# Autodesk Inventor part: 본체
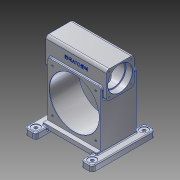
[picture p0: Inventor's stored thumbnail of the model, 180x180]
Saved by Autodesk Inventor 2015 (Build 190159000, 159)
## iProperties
Created: 2025-06
Part Number: 본체
Material: 알루미늄 6061
Document SubType Name: Modeling
Designer: User
Density: 2.7 g/cm^3
Appearance: 알루미늄 - 평지
Mass: 8003.18 g
Surface Area: 3446.16 cm^2
Volume: 2964.14 cm^3
Author: User
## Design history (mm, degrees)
sketch "스케치1"
  geometry: L1 (-93, 103)-(93, 103); L2 (93, 103)-(93, -103); L3 (93, -103)-(-93, -103); L4 (-93, -103)-(-93, 103); L5 (-93, 103)-(93, -103); L6 (93, 103)-(-93, -103); 1 further point
  constraints: 12 end point, 2 midpoint, 2 parallel, 1 horizontal, 1 perpendicular
  dimensions: "d0" = 186 distance of L2.end L3.end; "d1" = 206 distance of L1.end L2.end
extrude "돌출1" new body sketch "스케치1" stored distance "d2" = 140; taper "d3" = 0 deg
sketch "스케치3"
  geometry: L1 (0, 0)-(186, 0) reference; L2 (186, -140)-(0, -140) reference; L3 (201, -180)-(181, -180); L4 (171, -170)-(171, 30); L5 (181, 40)-(201, 40); L6 (211, 30)-(211, -170); L7 (93, -140)-(93, 0); L8 (15, -170)-(15, 30); L9 (-25, 30)-(-25, -170); L10 (-15, -180)-(5, -180); L11 (5, 40)-(-15, 40); A1 r 10 centre (201, -170) between (201, -180) and (211, -170); A2 r 10 centre (181, -170) between (171, -170) and (181, -180); A3 r 10 centre (201, 30) between (211, 30) and (201, 40); A4 r 10 centre (181, 30) between (181, 40) and (171, 30); A5 r 10 centre (-15, -170) between (-25, -170) and (-15, -180); A6 r 10 centre (5, -170) between (5, -180) and (15, -170); A7 r 10 centre (5, 30) between (15, 30) and (5, 40); A8 r 10 centre (-15, 30) between (-15, 40) and (-25, 30); 4 further points
  constraints: 18 end point, 16 point on circle, 13 symmetric about line, 8 centre point, 8 tangent, 4 midpoint, 3 equal radius, 2 parallel, 1 horizontal, 1 horizontal alignment, 1 perpendicular, 4 other
  dimensions: "d4" = 10 radius of A1; "d5" = 40 distance between parallel lines of L4 L6; "d6" = 118 distance from line of point (93, -70) L6; "d7" = 220 distance between parallel lines of L5 L3
extrude "돌출2" join sketch "스케치3" stored distance "d8" = 20; taper "d9" = 0 deg
sketch "스케치4"
  geometry: L1 (-211, -170)-(-211, 30) reference; L2 (-201, 40)-(-181, 40) reference; L3 (-171, 30)-(-171, 0) reference; L4 (-186, 0)-(-171, 0) reference; L5 (-186, -140)-(-186, 0) reference; L6 (-171, -140)-(-186, -140) reference; L7 (-15, -140)-(-171, -140) reference; L8 (-15, -170)-(-15, -140) reference; L9 (15, -180)-(-5, -180) reference; L10 (25, 30)-(25, -170) reference; L11 (-5, 40)-(15, 40) reference; L12 (-15, 0)-(-15, 30) reference; L13 (-15, 0)-(0, 0) reference; L14 (0, 0)-(0, -140) reference; L15 (0, -140)-(-15, -140) reference; L16 (-181, -180)-(-201, -180) reference; L17 (-171, -140)-(-171, -170) reference; L18 (-171, 0)-(-15, 0) reference; A1 r 10 centre (-201, -170) between (-211, -170) and (-201, -180) reference; A2 r 10 centre (-201, 30) between (-201, 40) and (-211, 30) reference; A3 r 10 centre (-181, 30) between (-171, 30) and (-181, 40) reference; A4 r 10 centre (-5, -170) between (-15, -170) and (-5, -180) reference; A5 r 10 centre (15, -170) between (15, -180) and (25, -170) reference; A6 r 10 centre (15, 30) between (25, 30) and (15, 40) reference; A7 r 10 centre (-5, 30) between (-5, 40) and (-15, 30) reference; A8 r 10 centre (-181, -170) between (-181, -180) and (-171, -170) reference; 5 further points
  constraints: 2 vertical alignment, 1 horizontal alignment
  dimensions: "d10" = 196 distance of point (5, 20) point (-191, 20); "d11" = 20 distance from line of point (5, 20) L12; "d12" = 180 distance of point (5, 20) point (5, -160); "d13" = 180 distance of point (-191, -160) point (-191, 20); "d14" = 90 vertical distance of point (5, 20) point (-93, -70)
hole "구멍1" sketch "스케치4" at (-191, -160), (-191, 20), (5, 20), (5, -160) diameter "d15" = 11; stored, may be unused: countersink angle "d19" = 90 deg, drill point angle "d21" = 118 deg; dims "d16" = 6, "d17" = 28, "d18" = 2, "d20" = 8
sketch "스케치5"
  geometry: L1 (93, -93)-(93, 103) reference; L2 (93, 103)-(-93, 103) reference; L3 (-93, 103)-(-93, -93) reference; L4 (-93, -86)-(93, -86); 1 further point
  constraints: 2 end point, 2 point on line, 1 perpendicular
  dimensions: "d22" = 189 distance between parallel lines of L4 L2
extrude "돌출3" cut sketch "스케치5" distance "d23" = 15; taper "d24" = 0 deg
sketch "스케치6"
  geometry: L1 (-70, -86)-(-55, -86) reference; L2 (-55, -86)-(-55, 103) reference; L3 (-55, 103)-(70, 103) reference; L4 (70, 103)-(70, -103) reference; L5 (70, -103)-(-70, -103) reference; L6 (-70, -103)-(-70, -86) reference; L7 (-38, 158)-(38, 158); L8 (48, 148)-(48, 72); L9 (38, 62)-(-38, 62); L10 (-48, 72)-(-48, 148); L11 (100, -113)-(-100, -113) reference; A1 r 10 centre (-38, 148) between (-38, 158) and (-48, 148); A2 r 10 centre (38, 148) between (48, 148) and (38, 158); A3 r 10 centre (38, 72) between (38, 62) and (48, 72); A4 r 10 centre (-38, 72) between (-48, 72) and (-38, 62); 6 further points
  constraints: 8 end point, 8 point on circle, 8 point on line, 8 tangent, 4 centre point, 3 equal radius, 2 parallel, 1 horizontal, 1 midpoint, 1 perpendicular, 1 vertical alignment
  dimensions: "d32" = 10 radius of A1; "d33" = 96 distance between parallel lines of L8 L10; "d34" = 96 distance between parallel lines of L9 L7; "d47" = 175 distance between parallel lines of L11 L9
extrude "돌출4" join sketch "스케치6" stored distance "d30" = 210; taper "d31" = 0 deg
sketch "스케치7"
  geometry: L1 (-88, -113)-(-108, -113) reference; C1 r 86 at (0, 10); 1 further point
  constraints: 1 centre point, 1 vertical alignment
  dimensions: "d35" = 172 diameter of C1; "d36" = 123 distance from line of L1 C1.centre
extrude "돌출5" cut sketch "스케치7" distance "d37" = 102; taper "d38" = 0 deg
sketch "스케치8"
  geometry: C1 r 86 at (0, 0) reference; 1 further point
hole "구멍2" sketch "스케치8" at (0, 0) diameter "d39" = 54; stored, may be unused: countersink angle "d43" = 90 deg, drill point angle "d45" = 0 deg; dims "d40" = 6, "d41" = 62, "d42" = 16, "d44" = 19
sketch "스케치9"
  geometry: L1 (76, 47)-(-96, 47) reference; L2 (76, -55)-(-96, -55) reference; L3 (76, -55)-(-96, -55) reference; L4 (86, -55)-(-103, -55) reference; L5 (-103, -55)-(86, -55) reference; L6 (21, 47)-(-41, 47) reference; L7 (76, 47)-(-96, 47) reference; L8 (76, -55)-(-96, -55) reference; L9 (113, 100)-(113, -100) reference; 2 further points
  constraints: 1 horizontal alignment
  dimensions: "d46" = 223 distance from line of L9 point (-110, 0)
hole "구멍3" sketch "스케치9" at (-110, 0) diameter "d48" = 77; stored, may be unused: countersink angle "d52" = 90 deg, drill point angle "d54" = 0 deg; dims "d49" = 6, "d50" = 85, "d51" = 23, "d53" = 19
sketch "스케치10"
  geometry: C1 r 38.5 at (110, 0) reference; C2 r 42.5 at (110, 0); 1 further point
  constraints: 1 centre point, 1 coincident
  dimensions: "d55" = 85 diameter of C2
extrude "돌출6" cut sketch "스케치10" distance "d56" = 23; taper "d57" = 0 deg
fillet "모깎기1" dims "d58" = 10
sketch "스케치11"
  geometry: C1 r 86 at (0, 10) reference; 5 further points
  constraints: 2 horizontal alignment, 2 vertical alignment
  dimensions: "d59" = 150 distance of point (75, 85) point (-75, 85); "d60" = 150 distance of point (75, -65) point (75, 85); "d61" = 75 horizontal distance of point (75, 85) C1.centre; "d62" = 75 horizontal distance of point (75, 85) C1.centre
hole "구멍4" sketch "스케치11" at (-75, -65), (75, -65), (75, 85), (-75, 85) diameter "d63" = 6.647; stored, may be unused: countersink angle "d67" = 90 deg, drill point angle "d69" = 118 deg; dims "d64" = 16, "d65" = 85, "d66" = 23, "d68" = 18
sketch "스케치12"
  geometry: A1 r 10 centre (-148, -38) between (-158, -38) and (-148, -48) reference; A2 r 10 centre (-72, -38) between (-72, -48) and (-62, -38) reference; A3 r 10 centre (-72, 38) between (-62, 38) and (-72, 48) reference; A4 r 10 centre (-148, 38) between (-148, 48) and (-158, 38) reference; 1 further point
hole "구멍5" sketch "스케치12" at (-148, -38), (-148, 38), (-72, 38), (-72, -38) diameter "d70" = 4.917; stored, may be unused: countersink angle "d74" = 90 deg, drill point angle "d76" = 118 deg; dims "d71" = 12, "d72" = 85, "d73" = 23, "d75" = 14
sketch "스케치13"
  geometry: A1 r 10 centre (148, 38) between (158, 38) and (148, 48) reference; A2 r 10 centre (72, 38) between (72, 48) and (62, 38) reference; A3 r 10 centre (72, -38) between (62, -38) and (72, -48) reference; A4 r 10 centre (148, -38) between (148, -48) and (158, -38) reference; 1 further point
hole "구멍6" sketch "스케치13" at (148, -38), (148, 38), (72, 38), (72, -38) diameter "d77" = 4.917; stored, may be unused: countersink angle "d81" = 90 deg, drill point angle "d83" = 118 deg; dims "d78" = 12, "d79" = 85, "d80" = 23, "d82" = 14
sketch "스케치14"
  geometry: L1 (0, 10)-(210, 10) reference; 2 further points
  constraints: 1 vertical alignment, 1 other
  dimensions: "d84" = 30 distance from line of point (105, -20) L1
feature "엠보싱1" sketch "스케치14" dims "d0" = 186, "d1" = 206, "d4" = 10, "d5" = 40, "d6" = 118, "d7" = 220, "d85" = 0.5, "d86" = 0
fillet "모깎기2" dims "d87" = 3
fillet "모깎기3" dims "d88" = 3
fillet "모깎기4" dims "d89" = 1
chamfer "모따기1" distance "d90" = 1; stored, may be unused: second distance "d91" = 2, angle "d92" = 45 deg
fillet "모깎기5" dims "d93" = 1.1
node "솔리드1"
node "투영된 루프1"
node "투영된 루프2"
node "투영된 루프3"
node "절단 모서리 투영2"
node "절단 모서리 투영3"
